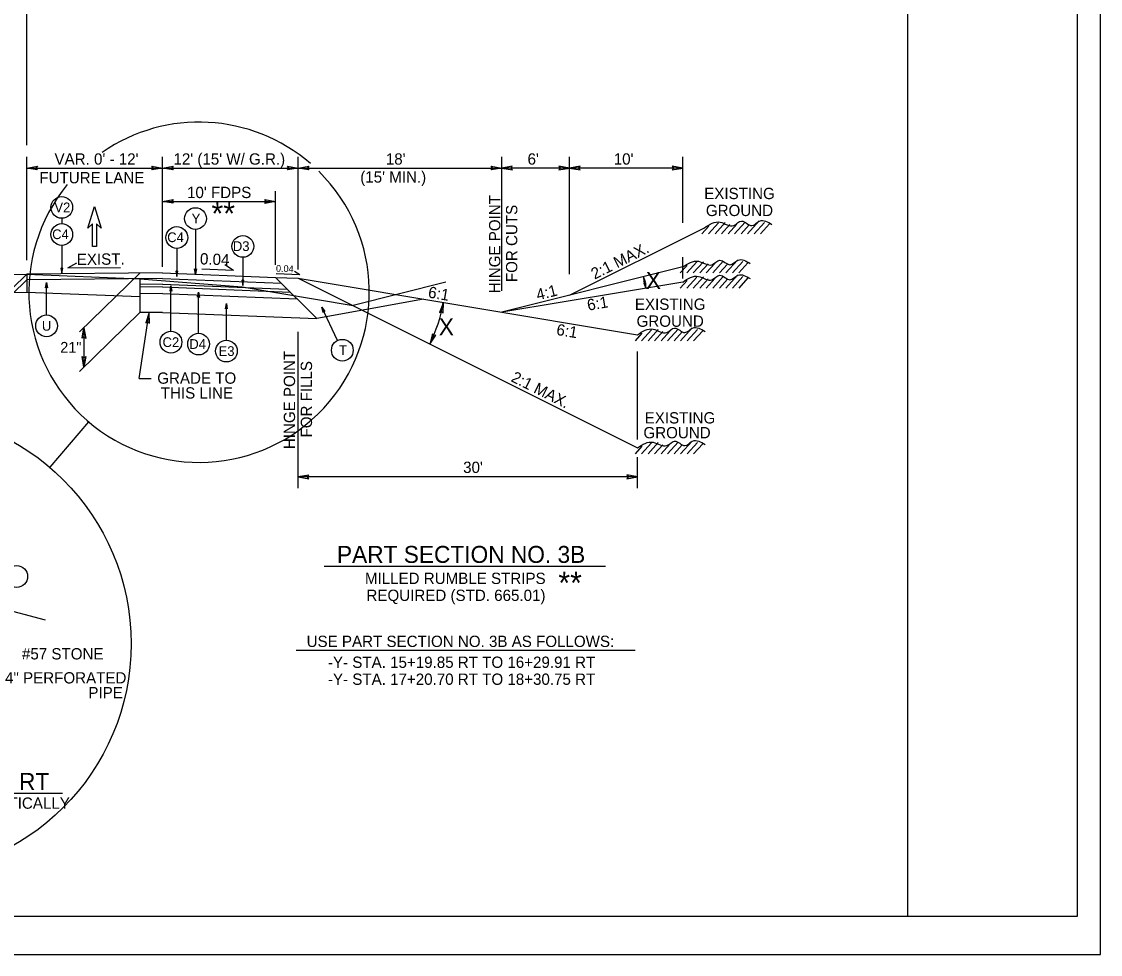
# Model space of a CAD drawing. Extents: x 1553884 to 1554215, y 810431 to 810779.
# Drawn here: x 1554061 to 1554156.4, y 810431 to 810513.5 of the extents above; entities that cross this region are included whole.
import ezdxf

# ---------------------------------------------------------------- set-up
doc = ezdxf.new("R2010")
doc.units = 0
for name, color, linetype in [('Old_Level_1', 7, 'Continuous'), ('Old_Level_15', 7, 'Continuous'), ('Old_Level_2', 7, 'Continuous'), ('Old_Level_20', 7, 'Continuous'), ('Prop Hatching', 7, 'Continuous'), ('Prop Lane Arrow CELL', 7, 'Continuous'), ('Prop Shade Light', 7, 'Continuous'), ('Sheet Plot Border Inside CELL', 7, 'Continuous'), ('Typical Arrow Superelevation CELL', 7, 'Continuous'), ('Typical Detail Pavement Repair CELL', 7, 'Continuous'), ('Typical Shoulder Slope CELL', 7, 'Continuous'), ('Typical Text ID Circle CELL', 7, 'Continuous')]:
    doc.layers.add(name, color=color, linetype=linetype)

msp = doc.modelspace()

# ---------------------------------------------------------------- linework, layer by layer
at = {"layer": 'Old_Level_1'}
msp.add_line((1554066.895, 810478.062), (1554063.457, 810474.031), dxfattribs=at)
msp.add_circle((1554050.156, 810458.432), 20.5, dxfattribs=at)
for start, end in [(49.11938, 124.69917), (140.71584, 45.35927)]:
    msp.add_arc((1554076.659, 810489.513), 15.049, start, end, dxfattribs=at)
at = {"layer": 'Old_Level_15'}
for points in [[(1554062.355, 810500.338), (1554061.417, 810500.499), (1554062.36, 810500.666), (1554062.24, 810500.499)], [(1554072.48, 810500.661), (1554073.417, 810500.499), (1554072.475, 810500.333), (1554072.594, 810500.499)], [(1554074.355, 810500.338), (1554073.417, 810500.499), (1554074.36, 810500.666), (1554074.24, 810500.499)], [(1554084.48, 810500.661), (1554085.417, 810500.499), (1554084.475, 810500.333), (1554084.594, 810500.499)], [(1554086.355, 810500.338), (1554085.417, 810500.499), (1554086.36, 810500.666), (1554086.24, 810500.499)], [(1554102.48, 810500.661), (1554103.417, 810500.499), (1554102.475, 810500.333), (1554102.594, 810500.499)], [(1554104.355, 810500.661), (1554103.417, 810500.499), (1554104.36, 810500.333), (1554104.24, 810500.499)], [(1554108.48, 810500.338), (1554109.417, 810500.499), (1554108.475, 810500.666), (1554108.594, 810500.499)], [(1554110.355, 810500.661), (1554109.417, 810500.499), (1554110.36, 810500.333), (1554110.24, 810500.499)], [(1554118.48, 810500.338), (1554119.417, 810500.499), (1554118.475, 810500.666), (1554118.594, 810500.499)], [(1554074.355, 810497.382), (1554073.417, 810497.544), (1554074.36, 810497.71), (1554074.24, 810497.544)], [(1554082.48, 810497.705), (1554083.417, 810497.544), (1554082.475, 810497.377), (1554082.594, 810497.544)], [(1554064.438, 810491.642), (1554064.519, 810491.173), (1554064.602, 810491.645), (1554064.519, 810491.585)], [(1554076.42, 810491.585), (1554076.34, 810491.116), (1554076.256, 810491.587), (1554076.34, 810491.527)], [(1554074.609, 810491.375), (1554074.69, 810490.906), (1554074.773, 810491.378), (1554074.69, 810491.318)], [(1554080.451, 810490.59), (1554080.532, 810490.122), (1554080.615, 810490.593), (1554080.532, 810490.533)], [(1554116.135, 810490.448), (1554115.948, 810490.886), (1554115.976, 810490.408), (1554116.043, 810490.485)], [(1554063.094, 810489.906), (1554063.175, 810490.375), (1554063.258, 810489.904), (1554063.175, 810489.964)], [(1554074.094, 810489.603), (1554074.175, 810490.072), (1554074.258, 810489.6), (1554074.175, 810489.66)], [(1554076.534, 810489.068), (1554076.615, 810489.536), (1554076.698, 810489.065), (1554076.615, 810489.125)], [(1554115.993, 810490.323), (1554116.158, 810489.876), (1554116.154, 810490.355), (1554116.083, 810490.281)], [(1554098.229, 810487.663), (1554098.255, 810488.613), (1554097.906, 810487.722), (1554098.093, 810487.807)], [(1554072.277, 810486.77), (1554072.258, 810487.721), (1554071.952, 810486.814), (1554072.135, 810486.908)], [(1554078.991, 810488.062), (1554079.072, 810488.53), (1554079.155, 810488.059), (1554079.072, 810488.119)], [(1554087.635, 810487.737), (1554087.505, 810488.195), (1554087.784, 810487.805), (1554087.683, 810487.823)], [(1554066.317, 810485.443), (1554066.478, 810486.381), (1554066.645, 810485.438), (1554066.478, 810485.558)], [(1554097.304, 810485.851), (1554097.058, 810484.933), (1554097.604, 810485.719), (1554097.402, 810485.68)], [(1554066.64, 810483.818), (1554066.478, 810482.881), (1554066.312, 810483.823), (1554066.478, 810483.704)], [(1554086.355, 810473.349), (1554085.417, 810473.187), (1554086.36, 810473.021), (1554086.24, 810473.187)], [(1554114.48, 810473.026), (1554115.417, 810473.187), (1554114.475, 810473.354), (1554114.594, 810473.187)]]:
    msp.add_lwpolyline(points, close=True, dxfattribs=at)
at = {"layer": 'Old_Level_2'}
for p, q in [((1554139.321, 810434.329), (1554139.325, 810592.576)), ((1554154.321, 810434.329), (1554154.325, 810592.576)), ((1553906.821, 810434.329), (1554154.321, 810434.329))]:
    msp.add_line(p, q, dxfattribs=at)
at = {"layer": 'Old_Level_20'}
for p, q in [((1554049.417, 810490.993), (1554061.417, 810491.113)), ((1554061.417, 810491.113), (1554058.181, 810487.947)), ((1554061.417, 810490.613), (1554058.181, 810487.447)), ((1554061.417, 810491.113), (1554061.417, 810489.528)), ((1554061.417, 810491.113), (1554071.417, 810490.713)), ((1554071.417, 810491.213), (1554066.1, 810486.01)), ((1554071.417, 810490.713), (1554071.417, 810489.128)), ((1554071.417, 810490.713), (1554080.463, 810489.989)), ((1554049.417, 810489.408), (1554061.417, 810489.528)), ((1554061.417, 810489.528), (1554071.417, 810489.128)), ((1554080.463, 810489.989), (1554090.291, 810488.351)), ((1554098.478, 810490.398), (1554090.291, 810488.351)), ((1554071.417, 810487.713), (1554066.1, 810482.51)), ((1554066.478, 810486.381), (1554066.478, 810482.881))]:
    msp.add_line(p, q, dxfattribs=at)
at = {"layer": 'Prop Hatching'}
msp.add_line((1554061.417, 810502.52), (1554061.417, 810517.168), dxfattribs=at)
msp.add_lwpolyline([(1554068.011, 810495.184), (1554067.605, 810495.559), (1554067.605, 810493.558), (1554067.23, 810493.558), (1554067.23, 810495.559), (1554066.824, 810495.184), (1554067.417, 810497.09)], close=True, dxfattribs=at)
at = {"layer": 'Prop Lane Arrow CELL'}
for p, q in [((1554156.35, 810430.954), (1554156.35, 810595.951)), ((1553901.353, 810430.954), (1554156.35, 810430.954))]:
    msp.add_line(p, q, dxfattribs=at)
at = {"layer": 'Prop Shade Light'}
for p, q in [((1554073.417, 810491.233), (1554061.417, 810491.113)), ((1554073.417, 810490.733), (1554061.417, 810490.613)), ((1554073.417, 810491.233), (1554083.417, 810490.833)), ((1554073.417, 810490.733), (1554083.938, 810490.312)), ((1554083.417, 810490.833), (1554087.063, 810487.187)), ((1554073.417, 810490.233), (1554071.417, 810490.213)), ((1554073.417, 810489.983), (1554071.417, 810489.963)), ((1554073.417, 810490.233), (1554084.459, 810489.791)), ((1554073.417, 810489.983), (1554084.719, 810489.531)), ((1554073.417, 810489.4), (1554071.417, 810489.38)), ((1554071.417, 810489.128), (1554071.417, 810487.713)), ((1554073.417, 810489.4), (1554085.327, 810488.923)), ((1554073.417, 810487.733), (1554071.417, 810487.713)), ((1554073.417, 810487.733), (1554087.063, 810487.187))]:
    msp.add_line(p, q, dxfattribs=at)
at = {"layer": 'Sheet Plot Border Inside CELL'}
for p, q in [((1554121.723, 810495.351), (1554121.122, 810494.682)), ((1554122.572, 810495.654), (1554121.698, 810494.682)), ((1554123.168, 810495.676), (1554122.274, 810494.682)), ((1554123.578, 810495.492), (1554122.85, 810494.682)), ((1554124.201, 810495.544), (1554123.426, 810494.682)), ((1554124.927, 810495.71), (1554124.002, 810494.682)), ((1554125.288, 810495.471), (1554124.578, 810494.682)), ((1554126.175, 810495.818), (1554125.154, 810494.682)), ((1554126.641, 810495.695), (1554125.73, 810494.682)), ((1554127.103, 810495.569), (1554126.306, 810494.682)), ((1554124.256, 810492.358), (1554123.235, 810491.223)), ((1554119.804, 810491.891), (1554119.203, 810491.223)), ((1554120.653, 810492.195), (1554119.779, 810491.223)), ((1554121.249, 810492.216), (1554120.355, 810491.223)), ((1554121.659, 810492.032), (1554120.931, 810491.223)), ((1554122.282, 810492.085), (1554121.507, 810491.223)), ((1554123.008, 810492.251), (1554122.083, 810491.223)), ((1554123.369, 810492.012), (1554122.659, 810491.223)), ((1554124.722, 810492.235), (1554123.811, 810491.223)), ((1554125.184, 810492.109), (1554124.387, 810491.223)), ((1554119.804, 810490.558), (1554119.203, 810489.889)), ((1554120.653, 810490.862), (1554119.779, 810489.889)), ((1554121.249, 810490.883), (1554120.355, 810489.889)), ((1554121.659, 810490.699), (1554120.931, 810489.889)), ((1554122.282, 810490.752), (1554121.507, 810489.889)), ((1554123.008, 810490.918), (1554122.083, 810489.889)), ((1554123.369, 810490.678), (1554122.659, 810489.889)), ((1554124.256, 810491.025), (1554123.235, 810489.889)), ((1554124.722, 810490.902), (1554123.811, 810489.889)), ((1554125.184, 810490.776), (1554124.387, 810489.889)), ((1554115.804, 810485.891), (1554115.203, 810485.223)), ((1554116.653, 810486.195), (1554115.779, 810485.223)), ((1554117.249, 810486.216), (1554116.355, 810485.223)), ((1554117.659, 810486.032), (1554116.931, 810485.223)), ((1554118.282, 810486.085), (1554117.507, 810485.223)), ((1554119.008, 810486.251), (1554118.083, 810485.223)), ((1554119.369, 810486.012), (1554118.659, 810485.223)), ((1554120.256, 810486.358), (1554119.235, 810485.223)), ((1554120.722, 810486.235), (1554119.811, 810485.223)), ((1554121.184, 810486.109), (1554120.387, 810485.223)), ((1554116.653, 810476.195), (1554115.779, 810475.223)), ((1554117.249, 810476.216), (1554116.355, 810475.223)), ((1554119.008, 810476.251), (1554118.083, 810475.223)), ((1554120.256, 810476.358), (1554119.235, 810475.223)), ((1554120.722, 810476.235), (1554119.811, 810475.223)), ((1554115.804, 810475.891), (1554115.203, 810475.223)), ((1554117.659, 810476.032), (1554116.931, 810475.223)), ((1554118.282, 810476.085), (1554117.507, 810475.223)), ((1554119.369, 810476.012), (1554118.659, 810475.223)), ((1554121.184, 810476.109), (1554120.387, 810475.223))]:
    msp.add_line(p, q, dxfattribs=at)
for points in [[(1554121.336, 810495.212), (1554122.73, 810495.711), (1554123.925, 810495.412), (1554124.623, 810495.811), (1554125.519, 810495.412), (1554126.216, 810495.811), (1554127.312, 810495.512)], [(1554119.417, 810491.753), (1554120.811, 810492.251), (1554122.007, 810491.952), (1554122.704, 810492.351), (1554123.6, 810491.952), (1554124.297, 810492.351), (1554125.393, 810492.052)], [(1554119.417, 810490.42), (1554120.811, 810490.918), (1554122.007, 810490.619), (1554122.704, 810491.018), (1554123.6, 810490.619), (1554124.297, 810491.018), (1554125.393, 810490.719)], [(1554115.417, 810485.753), (1554116.811, 810486.251), (1554118.007, 810485.952), (1554118.704, 810486.351), (1554119.6, 810485.952), (1554120.297, 810486.351), (1554121.393, 810486.052)], [(1554115.417, 810475.753), (1554116.811, 810476.251), (1554118.007, 810475.952), (1554118.704, 810476.351), (1554119.6, 810475.952), (1554120.297, 810476.351), (1554121.393, 810476.052)]]:
    msp.add_spline(points, degree=3, dxfattribs=at)
at = {"layer": 'Typical Arrow Superelevation CELL'}
for p, q in [((1554085.417, 810491.53), (1554085.417, 810501.499)), ((1554103.417, 810489.633), (1554103.417, 810501.499)), ((1554083.417, 810491.948), (1554083.417, 810498.458)), ((1554065.058, 810491.663), (1554065.846, 810492.128)), ((1554065.058, 810491.663), (1554069.719, 810491.709)), ((1554079.698, 810491.45), (1554076.903, 810491.562)), ((1554079.698, 810491.45), (1554078.925, 810491.939)), ((1554085.557, 810491.047), (1554083.487, 810491.13)), ((1554085.557, 810491.047), (1554085.092, 810491.341)), ((1554071.374, 810481.896), (1554072.258, 810487.721)), ((1554085.417, 810472.187), (1554085.417, 810486.008)), ((1554115.417, 810476.497), (1554115.417, 810484.274)), ((1554071.374, 810481.896), (1554072.435, 810481.896)), ((1554115.417, 810472.187), (1554115.417, 810474.943)), ((1554112.585, 810465.274), (1554087.711, 810465.274)), ((1554115.209, 810457.822), (1554085.251, 810457.822)), ((1554064.592, 810445.192), (1554035.719, 810445.192))]:
    msp.add_line(p, q, dxfattribs=at)
for centre, radius, start, end in [((1554103.417, 810487.753), 12.916, 9.46232, 14.03624), ((1554085.417, 810490.753), 13.014, 333.43495, 350.53768)]:
    msp.add_arc(centre, radius, start, end, dxfattribs=at)
at = {"layer": 'Typical Shoulder Slope CELL'}
for p, q in [((1554061.417, 810492.339), (1554061.417, 810501.499)), ((1554073.417, 810491.753), (1554073.417, 810501.499)), ((1554109.417, 810491.119), (1554109.417, 810501.499)), ((1554119.417, 810495.667), (1554119.417, 810501.499)), ((1554061.417, 810500.499), (1554073.417, 810500.499)), ((1554073.417, 810500.499), (1554085.417, 810500.499)), ((1554085.417, 810500.499), (1554103.417, 810500.499)), ((1554109.417, 810500.499), (1554103.417, 810500.499)), ((1554119.417, 810500.499), (1554109.417, 810500.499)), ((1554073.417, 810497.544), (1554083.417, 810497.544)), ((1554109.417, 810489.253), (1554121.336, 810495.212)), ((1554119.417, 810490.728), (1554119.417, 810492.619)), ((1554119.417, 810491.753), (1554103.417, 810487.753)), ((1554083.417, 810490.833), (1554085.417, 810490.753)), ((1554085.417, 810490.753), (1554115.417, 810485.753)), ((1554085.417, 810490.753), (1554115.417, 810475.753)), ((1554119.417, 810490.42), (1554103.417, 810487.753)), ((1554096.511, 810488.904), (1554087.063, 810487.187)), ((1554115.417, 810473.187), (1554085.417, 810473.187)), ((1554057.659, 810461.969), (1554063.06, 810460.551))]:
    msp.add_line(p, q, dxfattribs=at)
at = {"layer": 'Typical Text ID Circle CELL'}
for p, q in [((1554064.519, 810496.06), (1554064.519, 810495.582)), ((1554076.34, 810495.068), (1554076.34, 810491.116)), ((1554064.519, 810493.659), (1554064.519, 810491.173)), ((1554074.69, 810493.392), (1554074.69, 810490.906)), ((1554080.532, 810492.607), (1554080.532, 810490.122)), ((1554063.175, 810487.507), (1554063.175, 810490.375)), ((1554074.175, 810486.064), (1554074.175, 810490.072)), ((1554076.615, 810485.897), (1554076.615, 810489.536)), ((1554079.072, 810485.272), (1554079.072, 810488.53)), ((1554088.91, 810485.255), (1554087.505, 810488.195))]:
    msp.add_line(p, q, dxfattribs=at)
for centre in [(1554064.519, 810497.021), (1554076.34, 810496.029), (1554064.519, 810494.62), (1554074.69, 810494.353), (1554080.532, 810493.569), (1554063.175, 810486.546), (1554074.175, 810485.103), (1554076.615, 810484.935), (1554079.072, 810484.311), (1554089.325, 810484.387), (1554060.538, 810464.38)]:
    msp.add_circle(centre, 0.962, dxfattribs=at)

# ---------------------------------------------------------------- texts
at = {"layer": 'Old_Level_20'}
msp.add_text('21"', height=0.9558, dxfattribs=at).set_placement((1554064.385, 810484.163))
at = {"layer": 'Typical Arrow Superelevation CELL'}
for s, height, p in [("VAR. 0' - 12'", 1, (1554063.879, 810500.8)), ("12' (15' W/ G.R.)", 1, (1554074.395, 810500.8)), ("18'", 1, (1554093.171, 810500.8)), ("6'", 1, (1554105.702, 810500.8)), ("10'", 1, (1554113.322, 810500.8)), ('FUTURE LANE', 1, (1554062.539, 810499.147)), ("(15' MIN.)", 1, (1554090.91, 810499.212)), ("10' FDPS", 1, (1554075.595, 810497.844)), ('EXISTING', 1, (1554121.318, 810497.751)), ('**', 2, (1554077.757, 810495.481)), ('GROUND', 1, (1554121.467, 810496.251)), ('X', 1.5, (1554116.157, 810489.81)), ('EXISTING', 1, (1554115.191, 810487.959)), ('X', 1.5, (1554097.854, 810485.706)), ('GROUND', 1, (1554115.34, 810486.459)), ('GRADE TO ', 1, (1554072.962, 810481.423)), ('THIS LINE', 1, (1554073.273, 810480.112)), ('EXISTING', 1, (1554116.057, 810477.908)), ('GROUND', 1, (1554115.947, 810476.597)), ("30'", 1, (1554100.006, 810473.532)), ('PART SECTION NO. 3B', 1.5, (1554088.849, 810465.582)), ('MILLED RUMBLE STRIPS', 1, (1554091.324, 810463.713)), ('**', 2, (1554108.424, 810462.816)), ('REQUIRED (STD. 665.01)', 1, (1554091.458, 810462.213)), ('USE PART SECTION NO. 3B AS FOLLOWS:', 1, (1554086.168, 810458.142)), ('#57 STONE', 1, (1554061.002, 810457.041)), ('-Y- STA. 15+19.85 RT TO 16+29.91 RT', 1, (1554088.051, 810456.294)), ('4" PERFORATED', 1, (1554059.507, 810454.916)), ('-Y- STA. 17+20.70 RT TO 18+30.75 RT', 1, (1554088.051, 810454.794)), ('PIPE', 1, (1554066.872, 810453.605)), ('SHOULDER DRAIN INSET RT', 1.5, (1554035.774, 810445.501)), ('NOTE: DETAIL EXAGGERATED VERTICALLY', 1, (1554036.996, 810443.836))]:
    msp.add_text(s, height=height, dxfattribs=at).set_placement(p)
for s, height, rotation, p in [('HINGE POINT', 1, 90, (1554103.296, 810489.418)), ('FOR CUTS', 1, 90, (1554104.796, 810490.411)), ('2:1 MAX.', 1, 26.56505, (1554111.629, 810490.624)), ('EXIST.', 1, 0.57294, (1554065.85, 810491.921)), ('0.04', 1, 357.70939, (1554076.723, 810491.987)), ('0.04', 0.6, 357.70939, (1554083.449, 810491.337)), ('6:1', 1, 350.53768, (1554096.858, 810489.057)), ('4:1', 1, 14.03624, (1554106.604, 810488.79)), ('6:1', 1, 9.46232, (1554111.056, 810487.881)), ('6:1', 1, 350.53768, (1554108.199, 810485.752)), ('HINGE POINT', 1, 90, (1554085.148, 810475.639)), ('FOR FILLS', 1, 90, (1554086.648, 810476.671)), ('2:1 MAX.', 1, 333.43495, (1554104.165, 810481.674))]:
    msp.add_text(s, height=height, rotation=rotation, dxfattribs=at).set_placement(p)
at = {"layer": 'Typical Detail Pavement Repair CELL'}
for s, height, p in [('V2', 0.8608, (1554063.868, 810496.588)), ('Y', 0.861, (1554076.003, 810495.599)), ('C4', 0.8608, (1554063.67, 810494.214)), ('C4', 0.8608, (1554073.841, 810493.947)), ('D3', 0.8608, (1554079.648, 810493.162)), ('U', 0.861, (1554062.766, 810486.115)), ('C2', 0.8608, (1554073.432, 810484.672)), ('D4', 0.8608, (1554075.796, 810484.505)), ('E3', 0.8608, (1554078.384, 810483.88)), ('T', 0.861, (1554089.034, 810483.957))]:
    msp.add_text(s, height=height, dxfattribs=at).set_placement(p)

doc.saveas('drawing.dxf')
